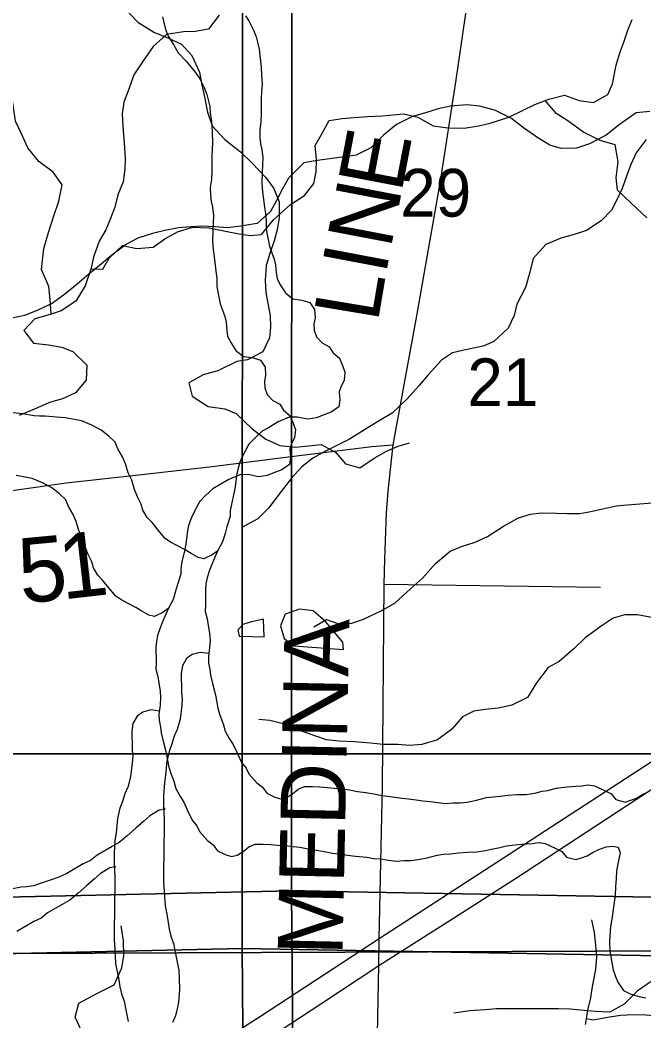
# Model space of a CAD drawing. Extents: x -21.1 to 50.3, y 0 to 22.1.
# Drawn here: x 6.598 to 7.145, y 17.901 to 18.778 of the extents above; entities that cross this region are included whole.
import ezdxf

# ---------------------------------------------------------------- set-up
doc = ezdxf.new("R2010")
doc.units = 0
for name, color, linetype in [('GM_X_County_Road', 7, 'Continuous'), ('GM_X_County_Road_Text', 7, 'Continuous'), ('GM_X_Interstate_Route', 7, 'Continuous'), ('GM_X_Minor_Lake', 7, 'Continuous'), ('GM_X_Minor_River', 7, 'Continuous'), ('GM_X_Section', 7, 'Continuous'), ('GM_X_Section_Text', 7, 'Continuous'), ('GM_X_Township_Road', 7, 'Continuous'), ('GM_X_Township_Road_Text', 7, 'Continuous')]:
    doc.layers.add(name, color=color, linetype=linetype)

msp = doc.modelspace()

# ---------------------------------------------------------------- linework, layer by layer
at = {"layer": 'GM_X_County_Road'}
msp.add_lwpolyline([(6.90953, 17.8137), (6.91225, 17.9491), (6.91231, 17.97286), (6.91522, 18.10644), (6.91693, 18.28359), (6.9174, 18.30509), (6.91896, 18.34592), (6.9202, 18.36508), (6.92457, 18.40584), (6.94533, 18.51888), (6.96609, 18.63686), (6.97979, 18.7259), (6.99194, 18.80809)], dxfattribs=at)
at = {"layer": 'GM_X_Interstate_Route'}
for points in [[(6.52734, 17.7228), (6.61326, 17.77751), (6.66427, 17.81148), (6.70057, 17.83571), (6.8083, 17.90468), (6.91231, 17.97286), (7.02146, 18.04363), (7.17586, 18.14395), (7.20054, 18.16004), (7.22207, 18.17407), (7.33433, 18.24726), (7.48634, 18.34577), (7.69968, 18.48506), (7.71733, 18.49655), (7.80078, 18.55084), (8.12382, 18.76024), (8.12551, 18.76133)], [(6.97836, 17.99127), (7.03276, 18.02598), (7.15587, 18.10652), (7.18773, 18.12735), (7.3625, 18.24092), (7.50936, 18.3366), (7.70132, 18.46121)], [(6.86133, 17.91555), (6.91225, 17.9491), (6.97836, 17.99127)], [(6.62028, 17.75763), (6.70018, 17.81138), (6.80791, 17.88035), (6.86133, 17.91555)]]:
    msp.add_lwpolyline(points, dxfattribs=at)
at = {"layer": 'GM_X_Minor_Lake'}
for points in [[(6.88114, 18.2262), (6.8807, 18.23265), (6.86536, 18.25074), (6.85465, 18.26014), (6.8425, 18.26155), (6.83001, 18.25725), (6.82593, 18.24695), (6.82907, 18.23596), (6.83757, 18.22942)], [(6.81108, 18.25289), (6.79934, 18.25012), (6.7929, 18.24816), (6.78839, 18.24318), (6.78958, 18.23787), (6.8116, 18.23732)], [(6.8116, 18.23732), (6.81108, 18.25289)], [(6.83757, 18.22942), (6.88114, 18.2262)]]:
    msp.add_lwpolyline(points, dxfattribs=at)
at = {"layer": 'GM_X_Minor_River'}
for points in [[(6.68822, 18.78948), (6.70099, 18.77643), (6.71532, 18.76717), (6.72515, 18.76365), (6.73913, 18.75705), (6.74814, 18.74709), (6.75482, 18.73258), (6.75699, 18.72154), (6.75952, 18.70936), (6.76205, 18.69756), (6.7661, 18.68537), (6.77699, 18.67348), (6.79092, 18.6627), (6.80107, 18.65272), (6.81271, 18.64045), (6.8202, 18.6305), (6.82463, 18.61868), (6.82487, 18.605), (6.82286, 18.59438), (6.82049, 18.58453), (6.81658, 18.57356), (6.81343, 18.56295), (6.81254, 18.55005), (6.81319, 18.5394), (6.81677, 18.51885), (6.81705, 18.50897), (6.81619, 18.49949), (6.81037, 18.48739), (6.79701, 18.48031), (6.78751, 18.47889), (6.7711, 18.4707), (6.75816, 18.46703), (6.74556, 18.45994), (6.74847, 18.44851), (6.76242, 18.43926), (6.77721, 18.43721), (6.78704, 18.43331), (6.80094, 18.41987), (6.813, 18.41064), (6.82547, 18.40519), (6.83912, 18.40353), (6.85052, 18.40494), (6.86154, 18.40596), (6.87437, 18.399), (6.883, 18.38903), (6.89549, 18.38549), (6.90811, 18.39409), (6.9188, 18.40006), (6.92909, 18.40452), (6.93899, 18.40746)], [(6.62488, 18.52046), (6.62413, 18.53305), (6.62289, 18.54444), (6.6163, 18.55958), (6.61841, 18.57783), (6.62246, 18.59193), (6.62726, 18.60641), (6.6317, 18.61937), (6.63461, 18.63384), (6.62654, 18.64478), (6.61393, 18.65416), (6.60434, 18.66623), (6.5993, 18.67796), (6.5935, 18.68969), (6.59148, 18.70372), (6.58986, 18.71435), (6.58821, 18.72915), (6.58432, 18.74051), (6.57928, 18.75225), (6.56853, 18.76544), (6.55738, 18.78167)], [(6.77216, 18.78257), (6.76278, 18.77032), (6.75104, 18.76831), (6.7408, 18.76783), (6.72602, 18.76541), (6.71435, 18.75504), (6.70498, 18.74165), (6.69749, 18.73018), (6.69305, 18.7176), (6.6886, 18.70616), (6.68717, 18.69627), (6.68766, 18.68488), (6.68892, 18.67045), (6.6898, 18.65716), (6.68951, 18.64766), (6.68809, 18.63625), (6.68326, 18.6248), (6.6807, 18.61414), (6.677, 18.60422), (6.67291, 18.59431), (6.66693, 18.58437), (6.66212, 18.57027), (6.65993, 18.56075), (6.65476, 18.54512), (6.64653, 18.53174), (6.6337, 18.52326), (6.62387, 18.52013), (6.61062, 18.51621), (6.60085, 18.50586), (6.60929, 18.49492), (6.62259, 18.49352), (6.63437, 18.49135), (6.64389, 18.48764), (6.65614, 18.4756), (6.6555, 18.4623), (6.64612, 18.45119), (6.63478, 18.44614), (6.62418, 18.443), (6.60868, 18.4364), (6.59696, 18.43135)], [(6.65972, 18.5601), (6.67019, 18.55971), (6.67579, 18.56926), (6.68746, 18.58039), (6.7, 18.57785), (6.71441, 18.57912), (6.72459, 18.58643), (6.73554, 18.59262), (6.74879, 18.59654), (6.76321, 18.59592), (6.77766, 18.59301), (6.78982, 18.59085), (6.79932, 18.58942), (6.80918, 18.59027), (6.81969, 18.60291), (6.83475, 18.61635), (6.84682, 18.62445), (6.85508, 18.63478), (6.85726, 18.64506), (6.85754, 18.6557), (6.85629, 18.66823), (6.8619, 18.67778), (6.86862, 18.69), (6.87999, 18.69201), (6.8906, 18.69287), (6.90236, 18.69374), (6.91526, 18.69424), (6.93384, 18.69594), (6.94639, 18.69302), (6.95973, 18.68554), (6.97265, 18.68376), (6.98707, 18.68352), (6.99958, 18.68554), (7.0098, 18.68792), (7.02608, 18.69301), (7.03817, 18.69882), (7.04874, 18.70424), (7.06122, 18.70892), (7.07485, 18.71247), (7.0878, 18.70765), (7.10034, 18.70586), (7.1128, 18.71282), (7.11689, 18.72236), (7.12016, 18.73873), (7.12347, 18.7494), (7.1268, 18.75893), (7.1305, 18.76922), (7.13421, 18.77876)], [(6.72244, 18.78108), (6.72478, 18.77121), (6.72749, 18.76401), (6.73209, 18.75682), (6.73632, 18.74962)], [(6.79532, 18.78199), (6.79839, 18.77707), (6.80224, 18.76949), (6.80456, 18.76343), (6.80611, 18.75774), (6.80728, 18.75281), (6.80769, 18.74711), (6.80848, 18.74218), (6.8089, 18.73648), (6.80931, 18.73002), (6.80974, 18.72167), (6.80939, 18.71559), (6.80905, 18.70913), (6.80912, 18.69621), (6.80878, 18.68899), (6.80768, 18.68177), (6.80772, 18.67531), (6.80851, 18.66962), (6.80968, 18.66468), (6.81048, 18.65747), (6.80979, 18.64455), (6.80946, 18.63543), (6.81027, 18.62746), (6.81106, 18.62101), (6.81186, 18.61379), (6.81265, 18.60848), (6.81345, 18.60241), (6.81349, 18.59519), (6.81428, 18.59025), (6.81624, 18.58001), (6.81817, 18.57508), (6.82049, 18.56863), (6.82166, 18.5637), (6.82208, 18.55649), (6.82287, 18.55155), (6.82557, 18.54587), (6.83017, 18.53905), (6.83667, 18.53377), (6.84467, 18.53268), (6.85154, 18.53044), (6.85576, 18.52438), (6.85618, 18.51717), (6.85507, 18.51184), (6.85548, 18.50615), (6.85741, 18.50046), (6.86239, 18.49517), (6.8685, 18.49178), (6.87196, 18.48648), (6.87769, 18.48158), (6.8804, 18.47513), (6.88233, 18.46945), (6.88161, 18.46222), (6.87897, 18.45727), (6.87748, 18.45232), (6.8779, 18.44511), (6.87717, 18.43902), (6.87034, 18.43443), (6.86237, 18.43135), (6.85743, 18.42942), (6.84982, 18.42824), (6.84068, 18.43009), (6.83345, 18.43005), (6.82395, 18.42582), (6.81485, 18.42045), (6.80991, 18.41776), (6.80348, 18.41165), (6.79818, 18.4063), (6.79215, 18.39449), (6.7899, 18.38954), (6.7884, 18.38421), (6.78729, 18.37889), (6.7862, 18.36901), (6.7851, 18.36292), (6.78286, 18.35379), (6.78176, 18.34771), (6.78179, 18.34277), (6.77879, 18.33364), (6.7773, 18.32793), (6.77506, 18.3207), (6.77091, 18.31308), (6.76866, 18.30775), (6.76565, 18.30089), (6.7634, 18.2948), (6.76153, 18.28909), (6.76042, 18.28377), (6.76006, 18.27883), (6.76014, 18.26516), (6.75979, 18.25945), (6.76173, 18.25301), (6.76252, 18.24731), (6.7637, 18.24048), (6.76412, 18.23441), (6.76377, 18.22795), (6.76268, 18.21996), (6.76271, 18.21464), (6.76388, 18.20857), (6.76467, 18.20364), (6.76623, 18.19643)], [(6.73632, 18.74962), (6.74283, 18.74244), (6.74743, 18.73715), (6.75203, 18.73147), (6.7551, 18.72655), (6.75895, 18.71898), (6.76127, 18.71291), (6.76282, 18.70722), (6.76399, 18.70229), (6.76441, 18.69659), (6.7652, 18.69166), (6.76561, 18.68596), (6.76602, 18.67951), (6.76645, 18.67115), (6.7661, 18.66507), (6.76576, 18.65861), (6.76583, 18.6457), (6.76549, 18.63848), (6.76439, 18.63125), (6.76443, 18.62479), (6.76522, 18.6191), (6.76639, 18.61417), (6.76719, 18.60696), (6.7665, 18.59404), (6.76617, 18.58492), (6.76698, 18.57694), (6.76777, 18.57049), (6.76858, 18.56328), (6.76937, 18.55796), (6.77016, 18.55189), (6.7702, 18.54467), (6.77099, 18.53974), (6.77295, 18.52949), (6.77488, 18.52456), (6.7772, 18.51812), (6.77837, 18.51319), (6.77879, 18.50597), (6.77958, 18.50104), (6.78228, 18.49535), (6.78688, 18.48854), (6.79338, 18.48326), (6.80138, 18.48216), (6.80825, 18.47992), (6.81247, 18.47386), (6.81289, 18.46665), (6.81178, 18.46133), (6.81219, 18.45563), (6.81413, 18.44994), (6.8191, 18.44465), (6.82521, 18.44127), (6.82867, 18.43597), (6.8344, 18.43106), (6.83711, 18.42462), (6.83904, 18.41893), (6.83832, 18.41171), (6.83568, 18.40675), (6.83419, 18.40181), (6.83461, 18.39459), (6.83388, 18.38851), (6.82706, 18.38391), (6.81908, 18.38083), (6.81414, 18.3789), (6.80653, 18.37772), (6.79739, 18.37957), (6.79016, 18.37953), (6.78067, 18.3753), (6.77156, 18.36993), (6.76663, 18.36725), (6.76019, 18.36113), (6.75489, 18.35579), (6.74886, 18.34397), (6.74661, 18.33902), (6.74512, 18.3337), (6.744, 18.32837), (6.74292, 18.31849), (6.74181, 18.31241), (6.73957, 18.30328), (6.73847, 18.29719), (6.7385, 18.29225), (6.7355, 18.28312), (6.73401, 18.27741), (6.73177, 18.27018), (6.72762, 18.26256), (6.72537, 18.25723), (6.72236, 18.25038), (6.72011, 18.24429), (6.71824, 18.23858), (6.71713, 18.23325), (6.71677, 18.22832), (6.71685, 18.21464), (6.7165, 18.20894), (6.71844, 18.20249), (6.71924, 18.1968), (6.72042, 18.18997), (6.72083, 18.18389), (6.72049, 18.17743), (6.71939, 18.16945), (6.71942, 18.16413), (6.72059, 18.15806), (6.72138, 18.15312), (6.72295, 18.14591)], [(7.05766, 18.70758), (7.06664, 18.69719), (7.07771, 18.69007), (7.09184, 18.67995), (7.10595, 18.67286), (7.11888, 18.66918), (7.12167, 18.65401), (7.1199, 18.63994), (7.12114, 18.62931), (7.13339, 18.61764), (7.14716, 18.60486)], [(7.14961, 18.69809), (7.13786, 18.69695), (7.12269, 18.68633), (7.11131, 18.67723), (7.0969, 18.66964), (7.08553, 18.66585), (7.07188, 18.66547), (7.06203, 18.6685), (7.05142, 18.67494), (7.03891, 18.68367), (7.0283, 18.69201), (7.01428, 18.69884), (7.00064, 18.70263), (6.98927, 18.70376), (6.97486, 18.70262), (6.96425, 18.70035), (6.95212, 18.69655), (6.9415, 18.69352), (6.92747, 18.68669), (6.9161, 18.6772), (6.9051, 18.66621), (6.89221, 18.65976), (6.88197, 18.65824), (6.87098, 18.65672), (6.85619, 18.65482), (6.84633, 18.65292), (6.83306, 18.63965), (6.82775, 18.63017), (6.82243, 18.61993), (6.81712, 18.61044), (6.80537, 18.59982), (6.79096, 18.59754), (6.77959, 18.59603), (6.7686, 18.59678), (6.75685, 18.59754), (6.74737, 18.59678), (6.73638, 18.59602), (6.72463, 18.59374), (6.71363, 18.59109), (6.70074, 18.58691), (6.69088, 18.5816), (6.67799, 18.57212), (6.66737, 18.56302), (6.65789, 18.55543), (6.64765, 18.54671), (6.63817, 18.53874), (6.62565, 18.52964), (6.61125, 18.52281), (6.60139, 18.51901), (6.5904, 18.51674)], [(7.14656, 18.67344), (7.13784, 18.66168), (7.1329, 18.65144), (7.12911, 18.6412), (7.12531, 18.63058), (7.12114, 18.6211), (7.1162, 18.61162), (7.1071, 18.60213), (7.09421, 18.59379), (7.08246, 18.58999), (7.0726, 18.58734), (7.05857, 18.58127), (7.04757, 18.56913), (7.04453, 18.55699), (7.04073, 18.54372), (7.03315, 18.52892), (7.03086, 18.51906), (7.02555, 18.50806), (7.01304, 18.49631), (7.00356, 18.49213), (6.98801, 18.4891), (6.97664, 18.48644), (6.96716, 18.47999), (6.9554, 18.46709), (6.94744, 18.45761), (6.93682, 18.44585), (6.92393, 18.43333)], [(6.7707, 18.31258), (6.76598, 18.30925), (6.75877, 18.3058), (6.75382, 18.30691), (6.74771, 18.31029), (6.74236, 18.31368), (6.73511, 18.31744), (6.72938, 18.32045), (6.72479, 18.32346), (6.7202, 18.32914), (6.7133, 18.33745), (6.70909, 18.34199), (6.70524, 18.34843), (6.70369, 18.35374), (6.70061, 18.36018), (6.69791, 18.36662), (6.69558, 18.37459), (6.6925, 18.38103), (6.69017, 18.38899), (6.68747, 18.39505), (6.68324, 18.40225), (6.68093, 18.40794), (6.67557, 18.41323), (6.66869, 18.41851), (6.66067, 18.42302), (6.65151, 18.42677), (6.63742, 18.42935), (6.62942, 18.43006), (6.61952, 18.43077), (6.61457, 18.43074), (6.61, 18.4311), (6.59971, 18.43294), (6.59171, 18.43366)], [(6.92393, 18.43333), (6.91331, 18.42727), (6.89966, 18.41892), (6.88639, 18.41058), (6.87653, 18.40564), (6.86477, 18.39995), (6.85416, 18.39388), (6.84468, 18.3863), (6.83557, 18.37643), (6.82647, 18.36468), (6.81547, 18.35026), (6.80599, 18.34078), (6.79196, 18.33319)], [(6.72741, 18.26206), (6.7227, 18.25874), (6.71548, 18.25528), (6.71053, 18.25639), (6.70442, 18.25978), (6.69907, 18.26317), (6.69182, 18.26693), (6.68609, 18.26993), (6.68151, 18.27295), (6.67691, 18.27862), (6.67001, 18.28694), (6.6658, 18.29147), (6.66195, 18.29791), (6.6604, 18.30322), (6.65732, 18.30966), (6.65462, 18.31611), (6.65229, 18.32407), (6.64921, 18.33051), (6.64688, 18.33848), (6.64418, 18.34454), (6.63995, 18.35173), (6.63764, 18.35742), (6.63228, 18.36271), (6.6254, 18.36799), (6.61738, 18.3725), (6.60823, 18.37625), (6.59413, 18.37883)], [(6.85522, 18.24597), (6.86621, 18.25242), (6.87607, 18.24901), (6.88857, 18.24939), (6.89881, 18.2528), (6.91474, 18.26039), (6.92649, 18.26722), (6.93976, 18.27935), (6.95038, 18.28884), (6.96176, 18.30173), (6.97465, 18.31235), (6.98451, 18.31653), (6.99664, 18.32032), (7.00726, 18.32525), (7.02129, 18.33436), (7.03456, 18.34156), (7.04518, 18.34498), (7.05465, 18.34612), (7.06754, 18.34574), (7.0774, 18.34536), (7.08839, 18.34536), (7.09786, 18.34726), (7.10962, 18.34992), (7.12023, 18.35219), (7.12971, 18.35295), (7.14108, 18.35409), (7.15549, 18.35523)], [(7.15278, 18.25397), (7.13875, 18.25662), (7.12776, 18.25662), (7.11753, 18.25358), (7.10691, 18.24676), (7.09288, 18.23651), (7.0834, 18.22703), (7.07012, 18.21565), (7.06065, 18.21034), (7.0504, 18.19706), (7.04244, 18.18417), (7.02879, 18.17734), (7.01665, 18.17469), (7.00528, 18.17354), (6.99543, 18.17203), (6.98557, 18.16709), (6.97609, 18.15647), (6.96357, 18.14699), (6.94992, 18.14282), (6.93931, 18.14206), (6.9287, 18.14282), (6.91581, 18.14281), (6.90482, 18.14395)], [(6.76306, 18.22273), (6.75542, 18.22372), (6.74858, 18.22178), (6.74365, 18.21834), (6.73988, 18.21186), (6.73878, 18.20502), (6.73881, 18.20008), (6.73922, 18.19476), (6.73925, 18.1883), (6.73967, 18.18299), (6.73932, 18.17729), (6.73786, 18.16513), (6.73525, 18.15599), (6.73261, 18.15028), (6.73075, 18.14343), (6.7285, 18.13772), (6.72626, 18.12859), (6.72519, 18.11605), (6.72409, 18.10921), (6.72339, 18.09818), (6.72344, 18.08907), (6.72389, 18.07767), (6.72396, 18.06476), (6.72361, 18.0583), (6.7237, 18.04234), (6.72335, 18.0374), (6.72339, 18.03095), (6.72344, 18.02183), (6.72386, 18.01423), (6.72469, 18.00132), (6.72587, 17.99563), (6.72705, 17.9888), (6.72823, 17.98083), (6.72979, 17.97476), (6.73211, 17.96831), (6.73367, 17.96073), (6.73564, 17.95048), (6.73681, 17.94517), (6.73723, 17.93757), (6.73728, 17.92807), (6.73658, 17.91705), (6.73547, 17.91097), (6.73399, 17.90488), (6.73135, 17.89917)], [(6.76623, 18.19643), (6.76818, 18.1896), (6.76935, 18.18467), (6.77092, 18.1748), (6.77286, 18.16873), (6.77557, 18.16115), (6.77751, 18.15471), (6.78097, 18.14827), (6.78442, 18.14297), (6.78751, 18.13615), (6.79174, 18.12705), (6.79596, 18.12214), (6.79827, 18.11721), (6.80517, 18.10927), (6.81014, 18.1055), (6.81397, 18.1002), (6.82084, 18.09682), (6.82618, 18.09533), (6.83112, 18.0965), (6.83643, 18.09957), (6.84136, 18.10377), (6.84706, 18.10608), (6.85391, 18.10612), (6.86038, 18.10577), (6.86685, 18.10505), (6.87333, 18.10471), (6.88018, 18.10398), (6.88628, 18.10326), (6.89352, 18.10178), (6.90076, 18.10068), (6.90761, 18.09958), (6.91485, 18.0981), (6.92209, 18.09738), (6.93238, 18.09591), (6.93809, 18.09519), (6.94495, 18.09446), (6.95066, 18.09335), (6.95714, 18.09301), (6.96399, 18.09191), (6.97047, 18.09118), (6.97732, 18.0916), (6.98379, 18.09164), (6.98949, 18.09243), (6.99786, 18.09399), (7.0066, 18.09632), (7.01231, 18.09711), (7.01839, 18.09753), (7.02524, 18.09832), (7.03323, 18.09913), (7.04122, 18.09917), (7.04883, 18.10035), (7.05529, 18.10191), (7.06024, 18.10269), (7.06746, 18.10463), (7.07735, 18.10583), (7.08496, 18.10625), (7.0899, 18.10665), (7.09561, 18.10745), (7.10132, 18.10672), (7.1101, 18.10259), (7.11583, 18.09958), (7.12004, 18.09466), (7.12805, 18.09243), (7.13299, 18.09398), (7.13793, 18.0959), (7.14324, 18.09897), (7.14817, 18.10128)], [(6.71977, 18.17222), (6.71213, 18.17321), (6.70529, 18.17127), (6.70037, 18.16782), (6.6966, 18.16134), (6.69549, 18.1545), (6.69552, 18.14956), (6.69593, 18.14425), (6.69596, 18.13779), (6.69638, 18.13247), (6.69603, 18.12677), (6.69457, 18.11461), (6.69196, 18.10548), (6.68933, 18.09976), (6.68746, 18.09292), (6.68521, 18.0872), (6.68298, 18.07808), (6.68191, 18.06553), (6.6808, 18.05869), (6.6801, 18.04767), (6.68015, 18.03855), (6.6806, 18.02716), (6.68067, 18.01424), (6.68032, 18.00778), (6.68041, 17.99183), (6.68006, 17.98689), (6.6801, 17.98043), (6.68015, 17.97131), (6.68057, 17.96372), (6.6814, 17.95081), (6.68258, 17.94511), (6.68376, 17.93828), (6.68495, 17.93031), (6.6865, 17.92424), (6.68882, 17.9178), (6.69038, 17.91021), (6.69235, 17.89996)], [(6.90482, 18.14395), (6.89079, 18.14509), (6.87715, 18.14584), (6.86615, 18.14698), (6.85592, 18.15039), (6.8419, 18.15532), (6.82939, 18.16063), (6.81651, 18.16404), (6.80703, 18.1648)], [(6.72295, 18.14591), (6.72489, 18.13909), (6.72606, 18.13415), (6.72763, 18.12429), (6.72957, 18.11822), (6.73228, 18.11064), (6.73422, 18.10419), (6.73768, 18.09775), (6.74113, 18.09245), (6.74422, 18.08563), (6.74845, 18.07654), (6.75267, 18.07162), (6.75498, 18.06669), (6.76188, 18.05875), (6.76685, 18.05498), (6.77068, 18.04968), (6.77755, 18.04631), (6.78289, 18.04481), (6.78783, 18.04598), (6.79314, 18.04905), (6.79807, 18.05326), (6.80377, 18.05557), (6.81062, 18.0556), (6.81709, 18.05526), (6.82356, 18.05454), (6.83004, 18.05419), (6.83689, 18.05347), (6.84299, 18.05274), (6.85023, 18.05126), (6.85747, 18.05016), (6.86433, 18.04906), (6.87156, 18.04758), (6.8788, 18.04686), (6.88909, 18.0454), (6.8948, 18.04467), (6.90166, 18.04395), (6.90737, 18.04284), (6.91385, 18.0425), (6.9207, 18.04139), (6.92718, 18.04067), (6.93403, 18.04109), (6.9405, 18.04112), (6.9462, 18.04191), (6.95457, 18.04348), (6.96331, 18.04581), (6.96902, 18.0466), (6.9751, 18.04701), (6.98195, 18.04781), (6.98994, 18.04861), (6.99793, 18.04865), (7.00554, 18.04983), (7.012, 18.05139), (7.01695, 18.05218), (7.02417, 18.05412), (7.03406, 18.05531), (7.04167, 18.05573), (7.04661, 18.05614), (7.05232, 18.05693), (7.05803, 18.0562), (7.06681, 18.05207), (7.07254, 18.04906), (7.07675, 18.04415), (7.08476, 18.04191), (7.0897, 18.04346), (7.09464, 18.04539), (7.09995, 18.04845), (7.10488, 18.05076), (7.11134, 18.05307), (7.11705, 18.05386), (7.122, 18.05275), (7.12355, 18.04782), (7.1217, 18.03832), (7.1206, 18.03185), (7.12025, 18.02539), (7.11953, 18.01817), (7.11919, 18.01057), (7.11773, 18.00031), (7.11626, 17.98966), (7.11516, 17.98358), (7.11447, 17.97028), (7.11451, 17.9623), (7.11609, 17.95319), (7.11765, 17.94522), (7.11959, 17.93954), (7.12152, 17.93461), (7.12651, 17.92704), (7.133, 17.92403), (7.14024, 17.92179), (7.14634, 17.92069)], [(6.72351, 18.08732), (6.7246, 18.08603), (6.71966, 18.08525), (6.71131, 18.08027), (6.70601, 18.07568), (6.69919, 18.06956), (6.69161, 18.06268), (6.68441, 18.05695), (6.67834, 18.05349), (6.66506, 18.04582), (6.65938, 18.04123), (6.65293, 18.03816), (6.64648, 18.03432), (6.63813, 18.02934), (6.63167, 18.02665), (6.62484, 18.02433), (6.6161, 18.02124), (6.60926, 18.01892), (6.60355, 18.01813), (6.59861, 18.01773), (6.58948, 18.01616)], [(6.68022, 18.03681), (6.68131, 18.03552), (6.67637, 18.03473), (6.66802, 18.02975), (6.66272, 18.02516), (6.6559, 18.01905), (6.64833, 18.01217), (6.64113, 18.00643), (6.63505, 18.00298), (6.62177, 17.99531), (6.61609, 17.99072), (6.60964, 17.98764), (6.60319, 17.98381), (6.59484, 17.97882)], [(7.09418, 17.90258), (7.09999, 17.9015), (7.11439, 17.90392), (7.12424, 17.90553), (7.13486, 17.90601), (7.14662, 17.90574), (7.1565, 17.90508), (7.16675, 17.90479), (7.1766, 17.9064), (7.18643, 17.90992), (7.19663, 17.91571), (7.21133, 17.92611), (7.22109, 17.9376), (7.22935, 17.94755), (7.23683, 17.96016), (7.24126, 17.97388), (7.24227, 17.98757), (7.24294, 17.99821), (7.25003, 18.01082), (7.25956, 18.02805)], [(7.09319, 17.89726), (7.09573, 17.91096), (7.09791, 17.92086), (7.09934, 17.93075), (7.10225, 17.9456), (7.10329, 17.95625), (7.10243, 17.96688), (7.10119, 17.97789), (7.09882, 17.98926)], [(6.65186, 17.89125), (6.64597, 17.90387), (6.6492, 17.91598), (6.6649, 17.92448), (6.68022, 17.93222), (6.6869, 17.94694), (6.68859, 17.95755), (6.68841, 17.97085), (6.68634, 17.9838)], [(7.15185, 17.93576), (7.13858, 17.92666), (7.1272, 17.91528), (7.11469, 17.90807), (7.1018, 17.90883), (7.08891, 17.90996), (7.07944, 17.91072), (7.06958, 17.9111), (7.01538, 17.91109), (7.00552, 17.91033), (6.99187, 17.90919), (6.97785, 17.90729)]]:
    msp.add_lwpolyline(points, dxfattribs=at)
at = {"layer": 'GM_X_Section'}
for points in [[(6.46467, 19.14528), (7.45853, 19.14217), (7.46215, 18.13462), (6.46827, 18.13471)], [(6.88772, 19.01332), (7.83142, 19.02525), (7.84977, 17.99671), (6.83569, 18.01448), (6.83581, 19.01172)], [(6.83581, 19.01172), (6.83569, 18.01448), (5.81893, 17.99203), (5.82494, 19.00715), (5.8818, 19.00728)], [(7.5274, 18.98311), (7.54061, 17.96333), (6.51666, 17.95921), (6.50457, 18.98884)], [(6.84443, 18.96281), (7.78814, 18.97473), (7.80649, 17.9462), (6.7924, 17.96396), (6.79252, 18.9612)], [(6.79252, 18.9612), (6.7924, 17.96396), (5.77564, 17.94152), (5.78166, 18.95663), (5.83851, 18.95676)], [(6.46827, 18.13471), (7.46215, 18.13462), (7.47526, 17.13233), (7.40705, 17.13199), (6.47301, 17.12604)], [(5.81893, 17.99203), (6.83569, 18.01448), (6.84408, 16.99761), (5.83147, 16.97938)], [(6.83569, 18.01448), (7.84977, 17.99671), (7.85852, 16.9825), (7.38497, 16.99642), (6.84408, 16.99761)], [(5.77564, 17.94152), (6.7924, 17.96396), (6.8008, 16.94709), (5.78818, 16.92886)], [(7.54061, 17.96333), (7.56617, 16.93816), (6.54146, 16.94121), (6.51666, 17.95921)], [(6.7924, 17.96396), (7.80649, 17.9462), (7.81523, 16.93198), (7.34169, 16.9459), (6.8008, 16.94709)]]:
    msp.add_lwpolyline(points, close=True, dxfattribs=at)
at = {"layer": 'GM_X_Township_Road'}
msp.add_line((6.91693, 18.28359), (7.10644, 18.28093), dxfattribs=at)
msp.add_lwpolyline([(6.52946, 18.35623), (6.58845, 18.36544), (6.63808, 18.37228), (6.70171, 18.37928), (6.76613, 18.38675), (6.82599, 18.39432), (6.90608, 18.40419), (6.92457, 18.40584)], dxfattribs=at)

# ---------------------------------------------------------------- texts
at = {"layer": 'GM_X_County_Road_Text'}
for s, height, rotation, p in [('E', 0.05682, 79.18763, (6.93184, 18.62573)), ('N', 0.05682, 79.19013, (6.92246, 18.57662)), ('I', 0.05682, 79.30698, (6.91813, 18.55372)), ('L', 0.05682, 80.51301, (6.91119, 18.51211)), ('MEDINA', 0.056818, 88.79254, (6.88021, 17.95738))]:
    msp.add_text(s, height=height, rotation=rotation, dxfattribs=at).set_placement(p)
at = {"layer": 'GM_X_Section_Text'}
for s, p in [('29', (6.93086, 18.60581)), ('21', (6.9897, 18.43963))]:
    msp.add_text(s, height=0.041856, rotation=0.00001, dxfattribs=at).set_placement(p)
at = {"layer": 'GM_X_Township_Road_Text'}
for s, rotation, p in [('1', 6.48211, (6.63474, 18.26996)), ('5', 5.43513, (6.59877, 18.26653))]:
    msp.add_text(s, height=0.05682, rotation=rotation, dxfattribs=at).set_placement(p)

doc.saveas('drawing.dxf')
